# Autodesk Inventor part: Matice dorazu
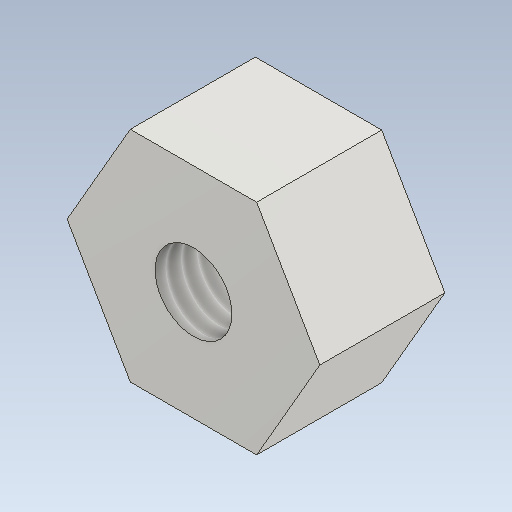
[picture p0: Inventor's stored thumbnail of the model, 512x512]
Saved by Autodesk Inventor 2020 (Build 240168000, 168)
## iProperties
Created: 2025-03
Part Number: Matice dorazu
Material: Ocel
Document SubType Name: Modeling
Designer: doma
Density: 7.85 g/cm^3
Appearance: Ocel
Mass: 9.46726 g
Surface Area: 8.13062 cm^2
Volume: 1.20602 cm^3
Author: doma
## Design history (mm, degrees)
sketch "Náčrt1"
  geometry: L1 (4.041, 7)-(8.083, 0); L2 (8.083, 0)-(4.041, -7); L3 (4.041, -7)-(-4.041, -7); L4 (-4.041, -7)-(-8.083, 0); L5 (-8.083, 0)-(-4.041, 7); L6 (-4.041, 7)-(4.041, 7); 2 further points
  constraints: 12 end point, 1 coincident, 13 other
  dimensions: "d0" = 14 distance between parallel lines of L3 L6
extrude "Vysunutí1" new body sketch "Náčrt1" distance "d1" = 8; taper "d2" = 0 deg
sketch "Náčrt2"
  geometry: 2 further points
  constraints: 1 coincident
hole "Díra1" sketch "Náčrt2" at (0, 0) diameter "d3" = 4.917; stored, may be unused: countersink angle "d7" = 90 deg, drill point angle "d9" = 118 deg; dims "d4" = 12, "d5" = 9, "d6" = 5, "d8" = 17.1
node "Těleso1"
